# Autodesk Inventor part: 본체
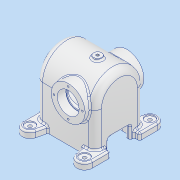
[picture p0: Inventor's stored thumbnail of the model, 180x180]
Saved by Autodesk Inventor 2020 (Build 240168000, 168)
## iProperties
Created: 2024-09
Part Number: 본체
Material: 알루미늄 6061
Document SubType Name: Modeling
Designer: oem
Density: 2.7 g/cm^3
Appearance: 알루미늄 - 평지
Mass: 1390.67 g
Surface Area: 1154.22 cm^2
Volume: 515.063 cm^3
Author: oem
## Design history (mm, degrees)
sketch "스케치1"
  geometry: L1 (0, 45)-(-76, 45); L2 (-76, 45)-(-76, -45); L3 (-76, -45)-(0, -45); L4 (0, -45)-(0, 45); A1 r 45 centre (0, 0) between (0, -45) and (0, 45); 1 further point
  constraints: 8 end point, 2 parallel, 2 point on circle, 2 tangent, 1 centre point, 1 coincident, 1 horizontal, 1 perpendicular
  dimensions: "d0" = 90 diameter of A1; "d1" = 76 distance between parallel lines of L2 L4
extrude "돌출1" new body sketch "스케치1" stored distance "d2" = 108; taper "d3" = 0 deg
feature "쉘1" dims "d5" = 9
node "작업 평면2"
sketch "스케치3"
  geometry: L1 (-22, -105)-(-22, -72); L2 (-22, -72)-(14, -72); L3 (14, -72)-(5.64, -108.154); L4 (106, -105)-(106, -72); L5 (106, -72)-(70, -72); L6 (70, -72)-(78.36, -108.154); L7 (-12, -90)-(96, -90) reference; L8 (-12, 0)-(-12, -90) reference; A1 r 14 centre (-8, -105) between (-22, -105) and (5.64, -108.154); A2 r 14 centre (92, -105) between (106, -105) and (78.36, -108.154); 3 further points
  constraints: 12 end point, 4 point on circle, 4 tangent, 2 centre point, 2 perpendicular, 2 vertical, 1 equal radius, 1 horizontal alignment, 1 midpoint
  dimensions: "d12" = 36 distance from line of L2.end L1; "d18" = 14 distance from line of A1.centre L1; "d19" = 100 distance of A2.centre A1.centre; "d20" = 128 distance between parallel lines of L4 L1; "d22" = 36 distance of L4.end L5.end; "d70" = 60 vertical distance of point (-12, -45) A1.centre; "d71" = 10 distance between parallel lines of L8 L1; "d72" = 18 distance between parallel lines of L2 L7
sketch "스케치14"
  geometry: L1 (-45, 0)-(-45, -76) reference; L2 (-45, -36)-(45, -36); L3 (-45, -45)-(45, -45); L4 (45, -76)-(45, 0) reference; L5 (-45, -36)-(-45, -45); L6 (45, -36)-(45, -45); L7 (-89.6, 0)-(89.6, 0) reference; 3 further points
  constraints: 8 end point, 4 point on line, 2 horizontal, 1 collinear, 1 parallel
  dimensions: "d67" = 45 distance from line of L3 point (0, 0); "d68" = 9 distance between parallel lines of L3 L2
revolve "회전2" sketch "스케치14" stored, may be unused: angle "d69" = 90 deg
extrude "돌출10" join sketch "스케치3" distance "d73" = 12; taper "d74" = 0 deg
node "작업 평면3"
sketch "스케치16"
  geometry: C1 r 28.5 at (0, 0); A1 r 45 centre (0, 0) between (45, 0) and (-45, 0) reference
  constraints: 1 centre point, 1 coincident
  dimensions: "d77" = 57 diameter of C1
extrude "돌출11" join sketch "스케치16" distance "d78" = 6; taper "d79" = 0 deg
sketch "스케치17"
  geometry: C1 r 28.5 at (0, 0) reference; C2 r 16.5 at (0, 0)
  constraints: 1 centre point, 1 coincident
  dimensions: "d80" = 33 diameter of C2
extrude "돌출12" cut sketch "스케치17" distance "d81" = 72; taper "d82" = 0 deg
sketch "스케치18"
  geometry: C1 r 16.5 at (0, 0) reference; 1 further point
  constraints: 1 vertical alignment
  dimensions: "d83" = 23 distance of C1.centre point (0, 23)
fillet "모깎기2" dims "d94" = 12
sketch "스케치19"
  geometry: L1 (-4, -1.5)-(-4, 55.5) reference; C1 r 7.5 at (-78, 27); 1 further point
  constraints: 1 centre point, 1 horizontal alignment
  dimensions: "d95" = 15 diameter of C1; "d96" = 74 distance from line of C1.centre L1
extrude "돌출13" join sketch "스케치19" stored distance "d97" = 72; taper "d98" = 0 deg
sketch "스케치20"
  geometry: C1 r 7.5 at (0, 0) reference; 2 further points
  constraints: 1 coincident
hole "구멍4" sketch "스케치20" at (0, 0) diameter "d99" = 5.1881; stored, may be unused: countersink angle "d103" = 60 deg, drill point angle "d105" = 118 deg; dims "d100" = 12, "d101" = 4.25, "d102" = 2, "d104" = 27.75
node "작업 평면4"
sketch "스케치21"
  geometry: L1 (42, 0)-(-42, 0) reference; L2 (60, -28.5)-(60, 28.5) reference; C1 r 31 at (-14, 0); 1 further point
  constraints: 1 centre point, 1 point on line
  dimensions: "d107" = 62 diameter of C1; "d108" = 74 distance from line of C1.centre L2
extrude "돌출14" join sketch "스케치21" stored distance "d109" = 72; taper "d110" = 0 deg
sketch "스케치22"
  geometry: C1 r 31 at (0, 0) reference; C2 r 20 at (0, 0); 1 further point
  constraints: 1 centre point, 1 coincident
  dimensions: "d111" = 40 diameter of C2
extrude "돌출15" cut sketch "스케치22" distance "d112" = 16; taper "d113" = 0 deg
sketch "스케치23"
  geometry: C1 r 20 at (0, 0) reference; 2 further points
  constraints: 1 vertical alignment
  dimensions: "d114" = 26 distance of C1.centre point (0, 26)
hole "구멍5" sketch "스케치23" at (0, 26) diameter "d115" = 3.242; stored, may be unused: countersink angle "d119" = 60 deg, drill point angle "d121" = 118 deg; dims "d116" = 8, "d117" = 4.25, "d118" = 2, "d120" = 10
sketch "스케치24"
  geometry: C1 r 20 at (0, 0) reference; C2 r 17.5 at (0, 0); 1 further point
  constraints: 1 centre point, 1 coincident
  dimensions: "d125" = 35 diameter of C2
extrude "돌출16" cut sketch "스케치24" distance "d126" = 44; taper "d127" = 0 deg
fillet "모깎기3" dims "d128" = 0.3
fillet "모깎기4" dims "d129" = 0.3
sketch "스케치25"
  geometry: L1 (-27, -76)-(27, -76) reference; A1 r 33 centre (0, 0) between (33, 0) and (-33, 0) reference; 1 further point
  constraints: 1 vertical alignment, 1 other
  dimensions: "d130" = 35 distance from line of point (0, -41) L1
feature "엠보싱1" sketch "스케치25" dims "d12" = 36, "d18" = 14, "d19" = 100, "d20" = 128, "d22" = 36, "d70" = 60, "d71" = 10, "d72" = 18, "d131" = 0.5, "d132" = 0
sketch "스케치26"
  geometry: A1 r 14 centre (92, 105) between (106, 105) and (78.36, 108.154) reference; A2 r 14 centre (92, -15) between (78.36, -18.154) and (106, -15) reference; A3 r 14 centre (-8, -15) between (-22, -15) and (5.64, -18.154) reference; 1 further point
hole "구멍6" sketch "스케치26" diameter "d133" = 6.6; stored, may be unused: countersink angle "d137" = 60 deg, drill point angle "d139" = 118 deg; dims "d134" = 8, "d135" = 18, "d136" = 2, "d138" = 10
hole "구멍7" sketch "스케치26" diameter "d140" = 6.6; stored, may be unused: countersink angle "d144" = 60 deg, drill point angle "d146" = 118 deg; dims "d141" = 8, "d142" = 18, "d143" = 2, "d145" = 10
sketch "스케치27"
  geometry: A1 r 14 centre (-8, 105) between (5.64, 108.154) and (-22, 105) reference; 1 further point
hole "구멍8" sketch "스케치27" at (-8, 105) diameter "d147" = 6.6; stored, may be unused: countersink angle "d151" = 60 deg, drill point angle "d153" = 118 deg; dims "d148" = 8, "d149" = 18, "d150" = 2, "d152" = 10
fillet "모깎기5" dims "d154" = 3
fillet "모깎기6" dims "d155" = 3
fillet "모깎기7" dims "d156" = 3
fillet "모깎기8" dims "d157" = 3
sketch "스케치28"
  geometry: L1 (20, -99)-(-20, -99); L2 (-20, -99)-(-20, -53); L3 (-20, -53)-(20, -53); L4 (20, -53)-(20, -99); L5 (27, -76)-(-27, -76) reference; L6 (20, -99)-(-20, -53); L7 (-20, -99)-(20, -53); 1 further point
  constraints: 12 end point, 3 midpoint, 2 parallel, 1 horizontal, 1 perpendicular
  dimensions: "d158" = 40 distance of L2.end L3.end; "d159" = 46 distance of L1.end L2.end
extrude "돌출17" cut sketch "스케치28" extent not by distance; stored distance "d160" = 0; taper "d161" = 0 deg
fillet "모깎기9" dims "d162" = 3
fillet "모깎기10" dims "d163" = 3
fillet "모깎기12" dims "d165" = 3
fillet "모깎기13" dims "d166" = 3
fillet "모깎기14" dims "d167" = 3
fillet "모깎기15" dims "d168" = 3
fillet "모깎기16" dims "d169" = 3
fillet "모깎기17" dims "d170" = 3
fillet "모깎기18" dims "d171" = 3
hole "구멍9" sketch "스케치18" diameter "d172" = 3.242; stored, may be unused: countersink angle "d176" = 82 deg, drill point angle "d178" = 118 deg; dims "d173" = 8, "d174" = 3.023, "d175" = 2, "d177" = 10
chamfer "모따기1" distance "d182" = 1; stored, may be unused: second distance "d183" = 2, angle "d184" = 45 deg
fillet "모깎기19" dims "d185" = 3
node "솔리드1"
mirror "미러2"
mirror "미러3"
pattern_circular "원형 패턴3" dims angle "d123" = 360 deg
mirror "미러4"
pattern_circular "원형 패턴4" dims angle "d180" = 360 deg
feature "A9D066F2-1C7D-4E18-AEED-F7BC21143FA4" dims "d133" = 6.6, "d134" = 8, "d135" = 18, "d136" = 2, "d137" = 60 deg, "d138" = 10, "d139" = 118 deg
other parameters: "d75" = -125, "d106" = -54
